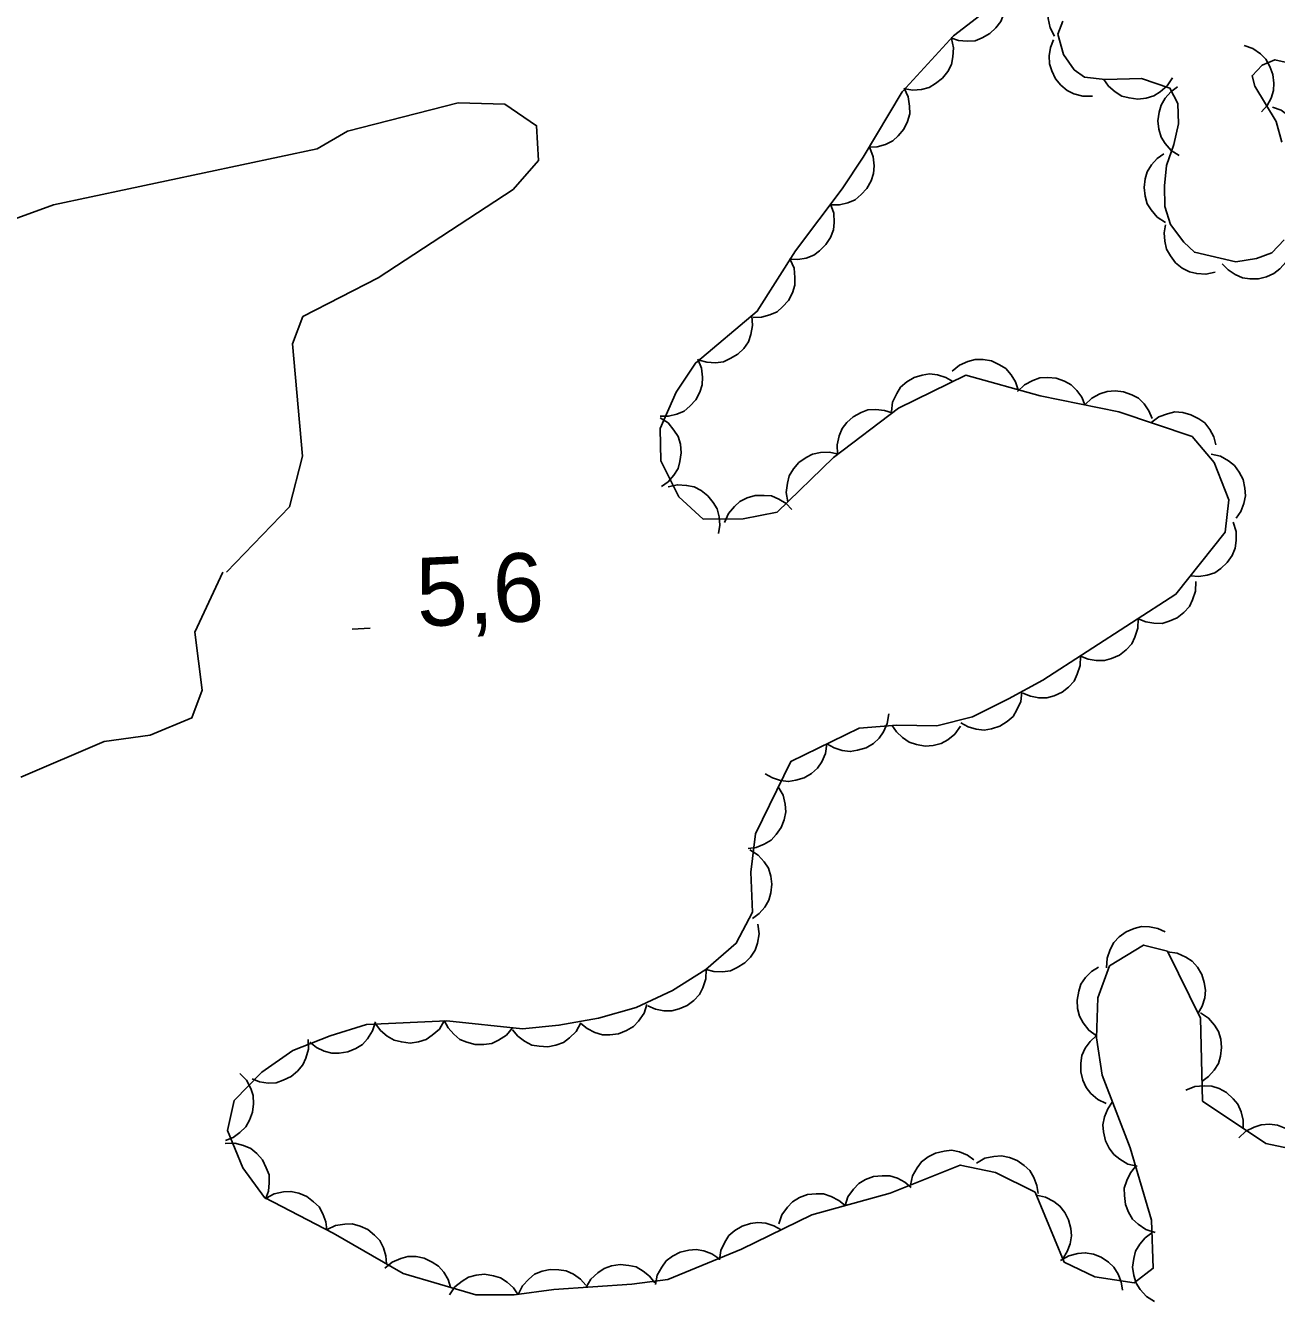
# Model space of a CAD drawing. Extents: x 336540 to 340074, y 5572036 to 5573747.
# Drawn here: x 337314.2 to 337369, y 5572759.6 to 5572815.4 of the extents above; entities that cross this region are included whole.
import ezdxf

# ---------------------------------------------------------------- set-up
doc = ezdxf.new("R2010")
doc.units = 0
for name, color, linetype in [('Niveau 1', 7, 'Continuous'), ('Niveau 3', 7, 'Continuous'), ('Niveau 44', 7, 'Continuous')]:
    doc.layers.add(name, color=color, linetype=linetype)

msp = doc.modelspace()

# ---------------------------------------------------------------- linework, layer by layer
at = {"layer": 'Niveau 1'}
for points in [[(337323.03, 5572791.48), (337325.78, 5572794.33), (337326.35, 5572796.55), (337325.91, 5572801.46), (337326.37, 5572802.65), (337329.66, 5572804.35), (337335.56, 5572808.21), (337336.67, 5572809.47), (337336.59, 5572810.99), (337335.2, 5572811.93), (337333.16, 5572811.99), (337328.32, 5572810.75), (337327, 5572809.98), (337315.46, 5572807.53), (337312.13, 5572806.33), (337308.92, 5572806.16), (337306.94, 5572805.56), (337301.35, 5572802.06)], [(337322.87, 5572791.47), (337321.65, 5572788.85), (337321.96, 5572786.32), (337321.52, 5572785.11), (337319.69, 5572784.35), (337317.68, 5572784.07), (337314.03, 5572782.52)]]:
    msp.add_lwpolyline(points, dxfattribs=at)
at = {"layer": 'Niveau 3'}
msp.add_line((337328.52, 5572788.99), (337329.32, 5572789.03), dxfattribs=at)
at = {"layer": 'Niveau 44'}
for points in [[(337359.24, 5572814.91), (337359.05, 5572815.28), (337358.97, 5572815.68), (337358.96, 5572816.01), (337359.04, 5572816.35), (337359.18, 5572816.69), (337359.42, 5572816.99), (337359.65, 5572817.23), (337359.96, 5572817.39), (337360.31, 5572817.51), (337360.66, 5572817.55)], [(337357.22, 5572816.78), (337354.83, 5572814.92), (337352.58, 5572812.48), (337350.88, 5572809.62), (337349.95, 5572808.24), (337347.92, 5572805.52), (337346.24, 5572802.88), (337343.54, 5572800.62), (337342.7, 5572799.35), (337342, 5572797.75), (337342.03, 5572796.34), (337342.81, 5572794.77), (337343.87, 5572793.8), (337345.62, 5572793.81), (337347.12, 5572794.1), (337349.57, 5572796.49), (337352.42, 5572798.65), (337355.37, 5572800.09), (337358.62, 5572799.18), (337362.06, 5572798.49), (337365.26, 5572797.4), (337366.23, 5572796.27), (337366.87, 5572794.64), (337366.71, 5572793.22), (337364.55, 5572790.51), (337358.73, 5572786.75), (337357.23, 5572785.94), (337355.66, 5572785.15), (337354.1, 5572784.76), (337352.34, 5572784.79), (337350.7, 5572784.65), (337347.71, 5572783.2), (337346.16, 5572780.04), (337345.96, 5572778.36), (337346.03, 5572776.61), (337345.32, 5572775.25), (337344, 5572774.1), (337342.54, 5572773.19), (337340.95, 5572772.45), (337339.3, 5572771.97), (337337.57, 5572771.67), (337335.97, 5572771.51), (337332.66, 5572771.86), (337329.15, 5572771.7)], [(337357.08, 5572816.67), (337357.11, 5572816.25), (337357.01, 5572815.86), (337356.9, 5572815.55), (337356.68, 5572815.27), (337356.41, 5572815.02), (337356.08, 5572814.84), (337355.77, 5572814.71), (337355.42, 5572814.69), (337355.05, 5572814.72), (337354.71, 5572814.83)], [(337369.29, 5572806.01), (337368.74, 5572805.43), (337368.07, 5572805.19), (337367.17, 5572805.05), (337365.36, 5572805.46), (337364.9, 5572805.9), (337364.32, 5572806.67), (337364.07, 5572807.46), (337364.05, 5572808.36), (337364.14, 5572809.26), (337364.46, 5572810.17), (337364.66, 5572811.07), (337364.64, 5572811.97), (337364.29, 5572812.64), (337363.04, 5572813.06), (337361.46, 5572813.02), (337360.56, 5572813.11), (337360.1, 5572813.44), (337359.64, 5572814.11), (337359.39, 5572815), (337359.6, 5572815.57)], [(337354.73, 5572814.81), (337354.82, 5572814.4), (337354.8, 5572814), (337354.73, 5572813.67), (337354.57, 5572813.36), (337354.34, 5572813.07), (337354.04, 5572812.84), (337353.76, 5572812.66), (337353.42, 5572812.58), (337353.05, 5572812.55), (337352.69, 5572812.6)], [(337360.9, 5572812.28), (337360.48, 5572812.28), (337360.09, 5572812.39), (337359.79, 5572812.53), (337359.52, 5572812.76), (337359.29, 5572813.04), (337359.13, 5572813.39), (337359.02, 5572813.7), (337359.01, 5572814.05), (337359.07, 5572814.42), (337359.2, 5572814.75)], [(337367.53, 5572814.5), (337367.92, 5572814.37), (337368.25, 5572814.13), (337368.49, 5572813.9), (337368.66, 5572813.59), (337368.79, 5572813.24), (337368.83, 5572812.86), (337368.82, 5572812.54), (337368.71, 5572812.2), (337368.54, 5572811.88), (337368.3, 5572811.6)], [(337369.78, 5572813.67), (337368.88, 5572813.88), (337368.32, 5572813.64), (337367.88, 5572813.18), (337368, 5572812.73), (337368.94, 5572811.18), (337369.19, 5572810.28)], [(337364.4, 5572813.09), (337364.17, 5572812.74), (337363.86, 5572812.48), (337363.58, 5572812.3), (337363.25, 5572812.2), (337362.88, 5572812.16), (337362.5, 5572812.21), (337362.18, 5572812.29), (337361.89, 5572812.48), (337361.61, 5572812.73), (337361.4, 5572813.02)], [(337352.67, 5572812.63), (337352.84, 5572812.25), (337352.9, 5572811.85), (337352.91, 5572811.51), (337352.81, 5572811.18), (337352.65, 5572810.84), (337352.4, 5572810.55), (337352.17, 5572810.33), (337351.85, 5572810.17), (337351.49, 5572810.07), (337351.13, 5572810.05)], [(337364.69, 5572809.69), (337364.34, 5572809.91), (337364.08, 5572810.22), (337363.9, 5572810.5), (337363.8, 5572810.84), (337363.76, 5572811.21), (337363.82, 5572811.59), (337363.9, 5572811.9), (337364.08, 5572812.2), (337364.33, 5572812.48), (337364.62, 5572812.69)], [(337368.77, 5572811.8), (337369.16, 5572811.67), (337369.49, 5572811.43), (337369.74, 5572811.21), (337369.91, 5572810.91), (337370.04, 5572810.56), (337370.08, 5572810.18), (337370.08, 5572809.85), (337369.97, 5572809.52), (337369.8, 5572809.19), (337369.57, 5572808.91)], [(337351.16, 5572810.03), (337351.31, 5572809.64), (337351.35, 5572809.24), (337351.33, 5572808.91), (337351.22, 5572808.58), (337351.04, 5572808.25), (337350.78, 5572807.98), (337350.53, 5572807.76), (337350.2, 5572807.63), (337349.84, 5572807.54), (337349.48, 5572807.54)], [(337364.09, 5572806.77), (337363.73, 5572807), (337363.47, 5572807.31), (337363.29, 5572807.58), (337363.2, 5572807.92), (337363.16, 5572808.29), (337363.21, 5572808.67), (337363.29, 5572808.98), (337363.48, 5572809.28), (337363.73, 5572809.56), (337364.02, 5572809.77)], [(337349.45, 5572807.57), (337349.59, 5572807.17), (337349.6, 5572806.77), (337349.57, 5572806.44), (337349.44, 5572806.11), (337349.24, 5572805.8), (337348.97, 5572805.53), (337348.71, 5572805.33), (337348.38, 5572805.21), (337348.01, 5572805.15), (337347.65, 5572805.16)], [(337366.27, 5572804.59), (337365.86, 5572804.5), (337365.46, 5572804.53), (337365.14, 5572804.6), (337364.83, 5572804.77), (337364.54, 5572805), (337364.31, 5572805.31), (337364.14, 5572805.59), (337364.07, 5572805.94), (337364.04, 5572806.31), (337364.1, 5572806.66)], [(337347.68, 5572805.14), (337347.85, 5572804.76), (337347.89, 5572804.36), (337347.89, 5572804.03), (337347.78, 5572803.69), (337347.61, 5572803.36), (337347.35, 5572803.08), (337347.11, 5572802.86), (337346.79, 5572802.72), (337346.43, 5572802.62), (337346.07, 5572802.61)], [(337369.55, 5572805.42), (337369.37, 5572805.04), (337369.1, 5572804.74), (337368.84, 5572804.53), (337368.52, 5572804.39), (337368.16, 5572804.3), (337367.78, 5572804.3), (337367.46, 5572804.34), (337367.14, 5572804.49), (337366.83, 5572804.7), (337366.58, 5572804.96)], [(337346, 5572802.68), (337346.04, 5572802.26), (337345.96, 5572801.86), (337345.86, 5572801.55), (337345.65, 5572801.26), (337345.39, 5572801), (337345.06, 5572800.81), (337344.76, 5572800.67), (337344.41, 5572800.63), (337344.04, 5572800.65), (337343.7, 5572800.75)], [(337343.65, 5572800.79), (337343.81, 5572800.4), (337343.85, 5572800), (337343.84, 5572799.67), (337343.73, 5572799.34), (337343.55, 5572799.01), (337343.29, 5572798.73), (337343.04, 5572798.52), (337342.72, 5572798.38), (337342.36, 5572798.29), (337342, 5572798.29)], [(337354.76, 5572800.26), (337355.08, 5572800.53), (337355.45, 5572800.69), (337355.77, 5572800.78), (337356.12, 5572800.78), (337356.48, 5572800.71), (337356.83, 5572800.54), (337357.11, 5572800.38), (337357.34, 5572800.11), (337357.54, 5572799.79), (337357.65, 5572799.45)], [(337352.11, 5572798.5), (337352.16, 5572798.91), (337352.34, 5572799.28), (337352.51, 5572799.56), (337352.78, 5572799.79), (337353.1, 5572799.98), (337353.46, 5572800.09), (337353.78, 5572800.14), (337354.13, 5572800.1), (337354.49, 5572799.99), (337354.8, 5572799.81)], [(337357.63, 5572799.38), (337357.93, 5572799.67), (337358.29, 5572799.86), (337358.6, 5572799.97), (337358.95, 5572799.99), (337359.32, 5572799.95), (337359.68, 5572799.82), (337359.97, 5572799.67), (337360.22, 5572799.42), (337360.43, 5572799.12), (337360.57, 5572798.79)], [(337360.57, 5572798.79), (337360.87, 5572799.08), (337361.23, 5572799.27), (337361.54, 5572799.38), (337361.89, 5572799.4), (337362.26, 5572799.36), (337362.62, 5572799.23), (337362.91, 5572799.08), (337363.16, 5572798.83), (337363.37, 5572798.53), (337363.51, 5572798.2)], [(337341.99, 5572798.22), (337342.34, 5572798), (337342.6, 5572797.69), (337342.78, 5572797.41), (337342.88, 5572797.07), (337342.92, 5572796.7), (337342.86, 5572796.32), (337342.78, 5572796.01), (337342.59, 5572795.71), (337342.35, 5572795.43), (337342.05, 5572795.22)], [(337349.75, 5572796.63), (337349.73, 5572797.04), (337349.82, 5572797.44), (337349.95, 5572797.75), (337350.16, 5572798.02), (337350.44, 5572798.27), (337350.78, 5572798.45), (337351.08, 5572798.57), (337351.43, 5572798.59), (337351.8, 5572798.55), (337352.14, 5572798.44)], [(337363.46, 5572798.01), (337363.8, 5572798.26), (337364.18, 5572798.4), (337364.5, 5572798.48), (337364.85, 5572798.45), (337365.21, 5572798.36), (337365.55, 5572798.18), (337365.82, 5572798), (337366.03, 5572797.72), (337366.21, 5572797.39), (337366.3, 5572797.04)], [(337347.58, 5572794.55), (337347.51, 5572794.96), (337347.56, 5572795.37), (337347.64, 5572795.69), (337347.82, 5572795.99), (337348.06, 5572796.27), (337348.38, 5572796.49), (337348.66, 5572796.64), (337349.01, 5572796.71), (337349.38, 5572796.72), (337349.73, 5572796.65)], [(337366.09, 5572796.63), (337366.5, 5572796.54), (337366.85, 5572796.34), (337367.11, 5572796.14), (337367.32, 5572795.85), (337367.49, 5572795.52), (337367.56, 5572795.15), (337367.6, 5572794.82), (337367.52, 5572794.48), (337367.39, 5572794.13), (337367.19, 5572793.84)], [(337342.34, 5572795.2), (337342.75, 5572795.3), (337343.15, 5572795.27), (337343.48, 5572795.21), (337343.79, 5572795.05), (337344.08, 5572794.82), (337344.32, 5572794.52), (337344.49, 5572794.24), (337344.57, 5572793.9), (337344.61, 5572793.53), (337344.55, 5572793.17)], [(337344.81, 5572793.65), (337344.98, 5572794.04), (337345.24, 5572794.35), (337345.48, 5572794.57), (337345.8, 5572794.72), (337346.15, 5572794.83), (337346.54, 5572794.83), (337346.86, 5572794.81), (337347.19, 5572794.67), (337347.5, 5572794.48), (337347.76, 5572794.22)], [(337367.06, 5572793.66), (337367.19, 5572793.26), (337367.19, 5572792.86), (337367.15, 5572792.53), (337367.01, 5572792.21), (337366.8, 5572791.9), (337366.52, 5572791.64), (337366.25, 5572791.45), (337365.92, 5572791.34), (337365.55, 5572791.29), (337365.19, 5572791.32)], [(337365.42, 5572791.07), (337365.41, 5572790.65), (337365.28, 5572790.27), (337365.14, 5572789.97), (337364.9, 5572789.71), (337364.61, 5572789.48), (337364.26, 5572789.33), (337363.95, 5572789.23), (337363.59, 5572789.24), (337363.23, 5572789.3), (337362.9, 5572789.44)], [(337362.9, 5572789.44), (337362.89, 5572789.02), (337362.76, 5572788.64), (337362.62, 5572788.34), (337362.38, 5572788.08), (337362.09, 5572787.85), (337361.74, 5572787.7), (337361.43, 5572787.61), (337361.07, 5572787.61), (337360.71, 5572787.67), (337360.38, 5572787.81)], [(337360.38, 5572787.81), (337360.37, 5572787.4), (337360.24, 5572787.01), (337360.1, 5572786.71), (337359.86, 5572786.45), (337359.57, 5572786.23), (337359.22, 5572786.07), (337358.91, 5572785.98), (337358.55, 5572785.98), (337358.19, 5572786.05), (337357.86, 5572786.19)], [(337357.82, 5572786.24), (337357.77, 5572785.82), (337357.6, 5572785.45), (337357.43, 5572785.17), (337357.17, 5572784.94), (337356.85, 5572784.75), (337356.49, 5572784.63), (337356.17, 5572784.57), (337355.82, 5572784.61), (337355.46, 5572784.72), (337355.14, 5572784.89)], [(337351.99, 5572785.28), (337351.93, 5572784.86), (337351.76, 5572784.5), (337351.58, 5572784.22), (337351.32, 5572783.99), (337351, 5572783.8), (337350.63, 5572783.69), (337350.31, 5572783.63), (337349.96, 5572783.68), (337349.61, 5572783.79), (337349.29, 5572783.97)], [(337355.13, 5572784.74), (337354.89, 5572784.4), (337354.57, 5572784.15), (337354.29, 5572783.98), (337353.94, 5572783.9), (337353.58, 5572783.87), (337353.2, 5572783.94), (337352.89, 5572784.04), (337352.6, 5572784.24), (337352.33, 5572784.49), (337352.13, 5572784.79)], [(337349.29, 5572783.97), (337349.23, 5572783.55), (337349.06, 5572783.19), (337348.88, 5572782.91), (337348.62, 5572782.68), (337348.3, 5572782.49), (337347.93, 5572782.38), (337347.61, 5572782.32), (337347.26, 5572782.37), (337346.91, 5572782.48), (337346.59, 5572782.66)], [(337347.16, 5572782.09), (337347.37, 5572781.72), (337347.46, 5572781.33), (337347.49, 5572781), (337347.42, 5572780.65), (337347.29, 5572780.31), (337347.07, 5572780), (337346.85, 5572779.76), (337346.55, 5572779.58), (337346.2, 5572779.44), (337345.84, 5572779.39)], [(337345.92, 5572779.33), (337346.28, 5572779.11), (337346.54, 5572778.81), (337346.73, 5572778.53), (337346.83, 5572778.19), (337346.88, 5572777.83), (337346.83, 5572777.45), (337346.75, 5572777.13), (337346.57, 5572776.83), (337346.33, 5572776.55), (337346.04, 5572776.33)], [(337346.27, 5572776.08), (337346.32, 5572775.66), (337346.25, 5572775.26), (337346.15, 5572774.95), (337345.95, 5572774.65), (337345.7, 5572774.39), (337345.37, 5572774.19), (337345.07, 5572774.05), (337344.72, 5572774), (337344.35, 5572774.01), (337344.01, 5572774.11)], [(337361.52, 5572774.18), (337361.54, 5572774.6), (337361.68, 5572774.98), (337361.83, 5572775.28), (337362.07, 5572775.53), (337362.37, 5572775.75), (337362.73, 5572775.89), (337363.04, 5572775.98), (337363.39, 5572775.97), (337363.76, 5572775.89), (337364.08, 5572775.75)], [(337329.15, 5572771.7), (337327.57, 5572771.2), (337325.93, 5572770.57), (337324.58, 5572769.62), (337323.36, 5572768.37), (337323.08, 5572767.06), (337323.74, 5572765.44), (337324.69, 5572764.13), (337327.7, 5572762.57), (337330.76, 5572760.81), (337333.94, 5572759.88), (337335.61, 5572759.88), (337337.34, 5572760.11), (337340.76, 5572760.34), (337342.33, 5572760.55), (337345.56, 5572761.88), (337348.63, 5572763.38), (337352.05, 5572764.32), (337355.12, 5572765.55), (337356.66, 5572765.23), (337358.39, 5572764.37), (337359.66, 5572761.31), (337361, 5572760.67), (337362.73, 5572760.4), (337363.56, 5572761.04), (337363.48, 5572763.14), (337362.55, 5572766.31), (337361.32, 5572769.48), (337361.08, 5572771.12), (337361.13, 5572772.87), (337361.65, 5572774.26), (337363.14, 5572775.17), (337364.18, 5572774.9), (337365.63, 5572771.98), (337365.71, 5572768.35), (337368.49, 5572766.49), (337370, 5572766.17)], [(337364.19, 5572774.87), (337364.61, 5572774.82), (337364.98, 5572774.65), (337365.26, 5572774.47), (337365.49, 5572774.21), (337365.68, 5572773.89), (337365.79, 5572773.53), (337365.85, 5572773.2), (337365.81, 5572772.86), (337365.7, 5572772.5), (337365.53, 5572772.19)], [(337344.01, 5572774.1), (337343.99, 5572773.69), (337343.86, 5572773.3), (337343.71, 5572773.01), (337343.47, 5572772.75), (337343.17, 5572772.53), (337342.82, 5572772.38), (337342.51, 5572772.29), (337342.15, 5572772.3), (337341.79, 5572772.37), (337341.46, 5572772.52)], [(337361.08, 5572771.21), (337360.74, 5572771.45), (337360.5, 5572771.77), (337360.33, 5572772.06), (337360.25, 5572772.4), (337360.23, 5572772.77), (337360.31, 5572773.15), (337360.4, 5572773.46), (337360.6, 5572773.75), (337360.86, 5572774.01), (337361.17, 5572774.2)], [(337341.41, 5572772.58), (337341.29, 5572772.19), (337341.05, 5572771.85), (337340.83, 5572771.61), (337340.53, 5572771.43), (337340.18, 5572771.29), (337339.8, 5572771.25), (337339.48, 5572771.25), (337339.14, 5572771.35), (337338.81, 5572771.52), (337338.53, 5572771.75)], [(337365.62, 5572772.21), (337365.98, 5572771.98), (337366.24, 5572771.67), (337366.42, 5572771.4), (337366.51, 5572771.06), (337366.55, 5572770.69), (337366.5, 5572770.31), (337366.42, 5572769.99), (337366.23, 5572769.7), (337365.98, 5572769.42), (337365.69, 5572769.21)], [(337329.54, 5572771.82), (337329.42, 5572771.42), (337329.2, 5572771.08), (337328.98, 5572770.83), (337328.68, 5572770.65), (337328.34, 5572770.5), (337327.96, 5572770.45), (337327.63, 5572770.44), (337327.3, 5572770.54), (337326.96, 5572770.69), (337326.68, 5572770.92)], [(337332.55, 5572771.86), (337332.34, 5572771.5), (337332.03, 5572771.23), (337331.76, 5572771.04), (337331.42, 5572770.94), (337331.06, 5572770.89), (337330.68, 5572770.94), (337330.36, 5572771.01), (337330.05, 5572771.19), (337329.77, 5572771.43), (337329.56, 5572771.72)], [(337335.54, 5572771.56), (337335.27, 5572771.24), (337334.93, 5572771.01), (337334.63, 5572770.87), (337334.28, 5572770.82), (337333.91, 5572770.83), (337333.54, 5572770.93), (337333.24, 5572771.05), (337332.97, 5572771.27), (337332.72, 5572771.55), (337332.55, 5572771.87)], [(337338.52, 5572771.77), (337338.32, 5572771.4), (337338.03, 5572771.11), (337337.77, 5572770.91), (337337.44, 5572770.79), (337337.08, 5572770.72), (337336.7, 5572770.75), (337336.38, 5572770.8), (337336.06, 5572770.97), (337335.77, 5572771.19), (337335.54, 5572771.47)], [(337326.6, 5572771.04), (337326.61, 5572770.62), (337326.5, 5572770.23), (337326.37, 5572769.93), (337326.14, 5572769.66), (337325.86, 5572769.42), (337325.51, 5572769.26), (337325.2, 5572769.15), (337324.85, 5572769.14), (337324.48, 5572769.19), (337324.15, 5572769.32)], [(337361.5, 5572768.24), (337361.13, 5572768.42), (337360.83, 5572768.69), (337360.62, 5572768.95), (337360.48, 5572769.27), (337360.39, 5572769.63), (337360.4, 5572770.01), (337360.44, 5572770.34), (337360.59, 5572770.66), (337360.8, 5572770.96), (337361.07, 5572771.2)], [(337323.61, 5572769.56), (337323.9, 5572769.26), (337324.09, 5572768.9), (337324.2, 5572768.59), (337324.21, 5572768.23), (337324.17, 5572767.87), (337324.03, 5572767.51), (337323.88, 5572767.22), (337323.62, 5572766.98), (337323.32, 5572766.76), (337322.99, 5572766.63)], [(337364.99, 5572768.83), (337365.38, 5572768.99), (337365.79, 5572769.02), (337366.12, 5572769.01), (337366.45, 5572768.9), (337366.77, 5572768.72), (337367.05, 5572768.45), (337367.26, 5572768.21), (337367.4, 5572767.88), (337367.49, 5572767.52), (337367.49, 5572767.16)], [(337362.86, 5572765.51), (337362.45, 5572765.6), (337362.1, 5572765.81), (337361.84, 5572766.01), (337361.63, 5572766.29), (337361.47, 5572766.62), (337361.39, 5572767), (337361.36, 5572767.32), (337361.43, 5572767.67), (337361.57, 5572768.01), (337361.77, 5572768.31)], [(337367.31, 5572766.74), (337367.61, 5572767.03), (337367.97, 5572767.21), (337368.28, 5572767.32), (337368.64, 5572767.34), (337369, 5572767.3), (337369.36, 5572767.16), (337369.65, 5572767.01), (337369.9, 5572766.75), (337370.11, 5572766.45), (337370.25, 5572766.12)], [(337322.97, 5572766.5), (337323.39, 5572766.51), (337323.78, 5572766.41), (337324.09, 5572766.28), (337324.36, 5572766.06), (337324.6, 5572765.78), (337324.77, 5572765.43), (337324.89, 5572765.13), (337324.9, 5572764.78), (337324.86, 5572764.41), (337324.73, 5572764.07)], [(337352.94, 5572764.68), (337353.03, 5572765.08), (337353.23, 5572765.44), (337353.42, 5572765.7), (337353.71, 5572765.91), (337354.04, 5572766.08), (337354.41, 5572766.16), (337354.73, 5572766.2), (337355.08, 5572766.13), (337355.43, 5572765.99), (337355.72, 5572765.79)], [(337355.83, 5572765.64), (337356.2, 5572765.85), (337356.59, 5572765.93), (337356.92, 5572765.96), (337357.27, 5572765.89), (337357.61, 5572765.76), (337357.92, 5572765.53), (337358.16, 5572765.31), (337358.34, 5572765.01), (337358.47, 5572764.66), (337358.52, 5572764.31)], [(337363.64, 5572762.61), (337363.24, 5572762.74), (337362.9, 5572762.97), (337362.66, 5572763.19), (337362.48, 5572763.49), (337362.34, 5572763.83), (337362.3, 5572764.22), (337362.29, 5572764.54), (337362.4, 5572764.88), (337362.56, 5572765.21), (337362.79, 5572765.49)], [(337350.08, 5572763.78), (337350.21, 5572764.17), (337350.45, 5572764.5), (337350.68, 5572764.75), (337350.98, 5572764.92), (337351.33, 5572765.05), (337351.71, 5572765.09), (337352.04, 5572765.09), (337352.37, 5572764.98), (337352.7, 5572764.81), (337352.97, 5572764.57)], [(337324.76, 5572764.1), (337325.12, 5572764.3), (337325.52, 5572764.38), (337325.85, 5572764.4), (337326.19, 5572764.32), (337326.54, 5572764.18), (337326.84, 5572763.95), (337327.08, 5572763.73), (337327.25, 5572763.42), (337327.38, 5572763.07), (337327.42, 5572762.72)], [(337347.19, 5572762.98), (337347.32, 5572763.38), (337347.56, 5572763.71), (337347.78, 5572763.95), (337348.09, 5572764.13), (337348.44, 5572764.26), (337348.82, 5572764.29), (337349.14, 5572764.29), (337349.48, 5572764.18), (337349.81, 5572764.01), (337350.08, 5572763.78)], [(337358.45, 5572764.24), (337358.85, 5572764.15), (337359.21, 5572763.96), (337359.48, 5572763.76), (337359.69, 5572763.48), (337359.86, 5572763.16), (337359.95, 5572762.78), (337359.99, 5572762.46), (337359.92, 5572762.11), (337359.79, 5572761.77), (337359.6, 5572761.46)], [(337327.43, 5572762.73), (337327.8, 5572762.91), (337328.2, 5572762.97), (337328.53, 5572762.98), (337328.87, 5572762.89), (337329.21, 5572762.74), (337329.5, 5572762.49), (337329.73, 5572762.26), (337329.89, 5572761.94), (337330, 5572761.59), (337330.03, 5572761.23)], [(337344.59, 5572761.41), (337344.65, 5572761.82), (337344.82, 5572762.19), (337345, 5572762.47), (337345.26, 5572762.7), (337345.58, 5572762.89), (337345.95, 5572763), (337346.27, 5572763.05), (337346.62, 5572763.01), (337346.97, 5572762.9), (337347.29, 5572762.72)], [(337363.62, 5572759.59), (337363.26, 5572759.81), (337362.99, 5572760.12), (337362.81, 5572760.39), (337362.71, 5572760.73), (337362.66, 5572761.09), (337362.71, 5572761.47), (337362.79, 5572761.79), (337362.97, 5572762.09), (337363.21, 5572762.37), (337363.5, 5572762.59)], [(337329.95, 5572761.05), (337330.27, 5572761.31), (337330.65, 5572761.47), (337330.96, 5572761.56), (337331.32, 5572761.55), (337331.68, 5572761.48), (337332.02, 5572761.31), (337332.3, 5572761.13), (337332.53, 5572760.87), (337332.72, 5572760.55), (337332.83, 5572760.21)], [(337341.79, 5572760.33), (337341.87, 5572760.74), (337342.07, 5572761.09), (337342.26, 5572761.36), (337342.54, 5572761.57), (337342.87, 5572761.74), (337343.25, 5572761.83), (337343.57, 5572761.86), (337343.91, 5572761.8), (337344.26, 5572761.67), (337344.56, 5572761.47)], [(337359.51, 5572761.38), (337359.87, 5572761.59), (337360.26, 5572761.69), (337360.59, 5572761.72), (337360.94, 5572761.66), (337361.28, 5572761.53), (337361.6, 5572761.31), (337361.84, 5572761.09), (337362.03, 5572760.79), (337362.16, 5572760.45), (337362.22, 5572760.09)], [(337335.78, 5572759.9), (337335.97, 5572760.28), (337336.25, 5572760.57), (337336.5, 5572760.78), (337336.83, 5572760.91), (337337.19, 5572760.99), (337337.57, 5572760.98), (337337.89, 5572760.93), (337338.21, 5572760.78), (337338.51, 5572760.57), (337338.75, 5572760.3)], [(337338.76, 5572760.21), (337338.97, 5572760.57), (337339.27, 5572760.84), (337339.54, 5572761.03), (337339.87, 5572761.15), (337340.24, 5572761.2), (337340.62, 5572761.16), (337340.94, 5572761.1), (337341.25, 5572760.92), (337341.53, 5572760.69), (337341.76, 5572760.41)], [(337332.78, 5572759.88), (337333.02, 5572760.23), (337333.33, 5572760.48), (337333.61, 5572760.65), (337333.95, 5572760.74), (337334.32, 5572760.78), (337334.7, 5572760.71), (337335.01, 5572760.62), (337335.31, 5572760.43), (337335.58, 5572760.18), (337335.78, 5572759.88)]]:
    msp.add_lwpolyline(points, dxfattribs=at)

# ---------------------------------------------------------------- texts
at = {"layer": 'Niveau 3'}
msp.add_text('5,6    ', height=3, rotation=2.7712, dxfattribs=at).set_placement((337331.4, 5572789.09))

doc.saveas('drawing.dxf')
